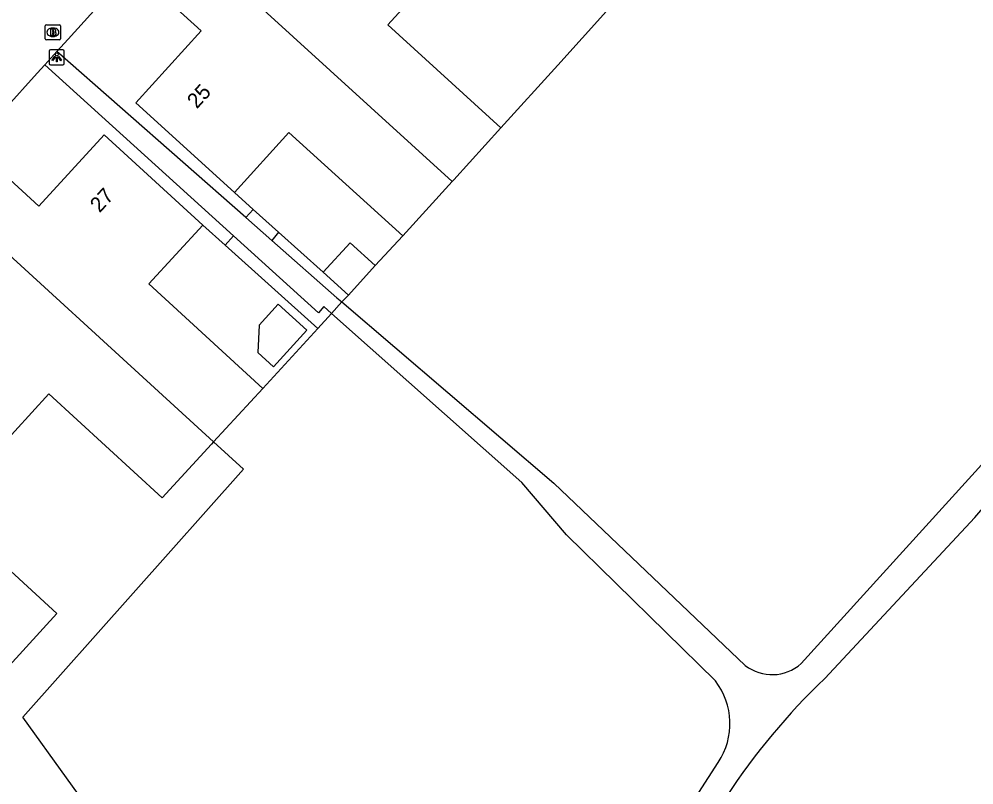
# Model space of a CAD drawing. Extents: x 158474 to 159560, y 388525 to 389605.
# Drawn here: x 158776 to 158838.9, y 389093.6 to 389144.1 of the extents above; entities that cross this region are included whole.
import ezdxf

# ---------------------------------------------------------------- set-up
doc = ezdxf.new("R2010")
doc.units = 0
for name, color, linetype in [('IMGEO_Brandkraan', 7, 'Continuous'), ('IMGEO_Erf', 7, 'Continuous'), ('IMGEO_Gemengd_bos', 7, 'Continuous'), ('IMGEO_Groenvoorziening', 7, 'Continuous'), ('IMGEO_Lichtpunt', 7, 'Continuous'), ('IMGEO_Loofbos', 7, 'Continuous'), ('IMGEO_Pand', 7, 'Continuous'), ('IMGEO_Pand_nummerreeks', 7, 'Continuous'), ('IMGEO_Rijbaan_lokaal_open', 7, 'Continuous'), ('IMGEO_Voetpad_halfverhard', 7, 'Continuous'), ('IMGEO_Voetpad_open', 7, 'Continuous')]:
    doc.layers.add(name, color=color, linetype=linetype)

msp = doc.modelspace()

# ---------------------------------------------------------------- linework, layer by layer
at = {"layer": 'IMGEO_Brandkraan'}
for p, q in [((158777.729, 389142.755), (158777.729, 389143.607)), ((158777.804, 389143.681), (158778.656, 389143.681)), ((158778.217, 389143.461), (158778.242, 389143.461)), ((158778.73, 389143.607), (158778.73, 389142.755)), ((158778.24, 389142.901), (158778.215, 389142.901)), ((158778.656, 389142.681), (158777.804, 389142.681))]:
    msp.add_line(p, q, dxfattribs=at)
for points in [[(158777.729, 389142.755), (158777.729, 389143.607)], [(158777.804, 389143.681), (158778.656, 389143.681)], [(158778.73, 389143.607), (158778.73, 389142.755)], [(158778.077, 389143.381), (158778.077, 389142.981), (158778.29, 389142.981)], [(158778.308, 389143.381), (158778.077, 389143.381)], [(158778.256, 389143.3), (158778.202, 389143.3), (158778.202, 389143.224)], [(158778.202, 389143.224), (158778.255, 389143.224)], [(158778.264, 389143.148), (158778.202, 389143.148), (158778.202, 389143.067)], [(158778.202, 389143.067), (158778.264, 389143.067)], [(158778.656, 389142.681), (158777.804, 389142.681)]]:
    msp.add_lwpolyline(points, dxfattribs=at)
for centre, radius, start, end in [((158777.806, 389143.605), 0.0765, 91.55205, 178.44795), ((158777.806, 389143.605), 0.0765, 91.55205, 178.44795), ((158778.654, 389143.605), 0.0765, 1.55205, 88.44795), ((158778.654, 389143.605), 0.0765, 1.55205, 88.44795), ((158778.257, 389143.262), 0.0379, 267.82845, 90.93552), ((158778.265, 389143.107), 0.0404, 269.87594, 90.50774), ((158778.296, 389143.232), 0.251, 268.66757, 293.53466), ((158778.312, 389143.236), 0.145, 59.4692, 91.53667), ((158778.337, 389143.283), 0.0922, 285.51372, 58.15012), ((158778.342, 389143.091), 0.105, 301.31148, 78.98903), ((158777.806, 389142.757), 0.0765, 181.55205, 268.44795), ((158777.806, 389142.757), 0.0765, 181.55205, 268.44795), ((158778.654, 389142.757), 0.0765, 271.55205, 358.44795), ((158778.654, 389142.757), 0.0765, 271.55205, 358.44795)]:
    msp.add_arc(centre, radius, start, end, dxfattribs=at)
for centre, major_axis, ratio, start_param, end_param in [((158778.216, 389143.181), (-0.387, 0.002), 0.722429, 4.712389, 7.853982), ((158778.241, 389143.181), (-0.39, 0.002), 0.717154, 1.570796, 4.712389)]:
    msp.add_ellipse(centre, major_axis=major_axis, ratio=ratio, start_param=start_param, end_param=end_param, dxfattribs=at)
at = {"layer": 'IMGEO_Erf'}
for points in [[(158790.19, 389132.623), (158791.426, 389131.502)], [(158789.58, 389129.136), (158788.104, 389130.461)]]:
    msp.add_lwpolyline(points, dxfattribs=at)
at = {"layer": 'IMGEO_Gemengd_bos'}
for points in [[(158807.753, 389136.882), (158811.49, 389141.014), (158814.701, 389144.565)], [(158801.279, 389129.76), (158799.471, 389127.8)], [(158797.699, 389125.851), (158797.266, 389125.409)]]:
    msp.add_lwpolyline(points, dxfattribs=at)
at = {"layer": 'IMGEO_Groenvoorziening'}
for points in [[(158790.125, 389129.762), (158789.58, 389129.136)], [(158796.041, 389127.359), (158793.089, 389129.994)], [(158795.685, 389123.654), (158789.58, 389129.136)]]:
    msp.add_lwpolyline(points, dxfattribs=at)
at = {"layer": 'IMGEO_Lichtpunt'}
for p, q in [((158777.985, 389141.933), (158777.985, 389141.126)), ((158777.985, 389141.933), (158777.985, 389141.126)), ((158778.887, 389142.028), (158778.079, 389142.028)), ((158778.887, 389142.028), (158778.079, 389142.028)), ((158778.981, 389141.126), (158778.981, 389141.933)), ((158778.981, 389141.126), (158778.981, 389141.933)), ((158778.079, 389141.032), (158778.887, 389141.032)), ((158778.079, 389141.032), (158778.887, 389141.032))]:
    msp.add_line(p, q, dxfattribs=at)
for points in [[(158778.359, 389141.597), (158778.398, 389141.569), (158778.21, 389141.307), (158778.172, 389141.334), (158778.359, 389141.597)], [(158778.461, 389141.549), (158778.508, 389141.549), (158778.508, 389141.227), (158778.461, 389141.227), (158778.461, 389141.549)], [(158778.571, 389141.569), (158778.609, 389141.596), (158778.796, 389141.334), (158778.757, 389141.306), (158778.571, 389141.569)]]:
    msp.add_lwpolyline(points, dxfattribs=at)
msp.add_circle((158778.484, 389141.731), 0.0994, dxfattribs=at)
for centre, start, end in [((158778.079, 389141.933), 90, 180), ((158778.079, 389141.933), 90, 180), ((158778.887, 389141.933), 0, 90), ((158778.887, 389141.933), 0, 90), ((158778.079, 389141.126), 180, 270), ((158778.079, 389141.126), 180, 270), ((158778.887, 389141.126), 270, 0), ((158778.887, 389141.126), 270, 360)]:
    msp.add_arc(centre, 0.0946, start, end, dxfattribs=at)
at = {"layer": 'IMGEO_Loofbos'}
for points in [[(158796.579, 389124.646), (158795.685, 389123.654)], [(158795.685, 389123.654), (158792.058, 389119.706)], [(158781.994, 389090.017), (158776.247, 389098.029), (158790.784, 389114.383), (158788.821, 389116.176)]]:
    msp.add_lwpolyline(points, dxfattribs=at)
at = {"layer": 'IMGEO_Pand'}
for points in [[(158786.016, 389150.231), (158804.546, 389133.353)], [(158790.19, 389132.623), (158783.685, 389138.536), (158788.004, 389143.287), (158783.46, 389147.419)], [(158803.803, 389147.531), (158800.29, 389143.666), (158807.753, 389136.882)], [(158801.279, 389129.76), (158793.782, 389136.575), (158790.19, 389132.623)], [(158807.753, 389136.882), (158804.643, 389133.46), (158804.546, 389133.353)], [(158772.904, 389135.737), (158777.295, 389131.711), (158781.609, 389136.416), (158788.104, 389130.461)], [(158804.546, 389133.353), (158801.279, 389129.76)], [(158770.397, 389133.003), (158788.821, 389116.176)], [(158788.104, 389130.461), (158784.552, 389126.588), (158792.058, 389119.706)], [(158799.471, 389127.8), (158797.812, 389129.308), (158796.041, 389127.359)], [(158799.471, 389127.8), (158797.699, 389125.851)], [(158796.041, 389127.359), (158797.699, 389125.851)], [(158791.738, 389122.062), (158792.76, 389121.133), (158794.954, 389123.547), (158793.08, 389125.251), (158791.824, 389123.87), (158791.738, 389122.062)], [(158792.058, 389119.706), (158788.821, 389116.176)], [(158788.821, 389116.176), (158788.679, 389116.021), (158785.432, 389112.48), (158777.954, 389119.336), (158774.578, 389115.654)], [(158774.578, 389115.654), (158770.989, 389111.741), (158778.5, 389104.854), (158775.345, 389101.412)]]:
    msp.add_lwpolyline(points, dxfattribs=at)
at = {"layer": 'IMGEO_Rijbaan_lokaal_open'}
for points in [[(158778.486, 389141.915), (158779.226, 389142.733), (158783.46, 389147.419)], [(158777.698, 389141.042), (158778.486, 389141.915)], [(158772.904, 389135.737), (158777.199, 389140.49), (158777.698, 389141.042)]]:
    msp.add_lwpolyline(points, dxfattribs=at)
at = {"layer": 'IMGEO_Voetpad_halfverhard'}
for points in [[(158827.533, 389101.555), (158846.783, 389122.782), (158849.381, 389126.955)], [(158797.266, 389125.409), (158811.239, 389113.455), (158823.843, 389101.437)], [(158829.083, 389100.567), (158838.982, 389111.199), (158851.235, 389125.547), (158852.333, 389125.541)], [(158821.882, 389100.424), (158812.081, 389110.051), (158809.123, 389113.496), (158796.579, 389124.646)], [(158817.024, 389087.185), (158822.071, 389095.043)]]:
    msp.add_lwpolyline(points, dxfattribs=at)
for centre, radius, start, end in [((158825.617, 389103.727), 2.897, 232.24525, 311.41794), ((158818.206, 389097.601), 4.635, 326.50107, 37.52214), ((158859.453, 389068.679), 44.036, 133.60357, 146.77948)]:
    msp.add_arc(centre, radius, start, end, dxfattribs=at)
at = {"layer": 'IMGEO_Voetpad_open'}
for points in [[(158790.937, 389130.966), (158778.486, 389141.915)], [(158777.698, 389141.042), (158790.125, 389129.762)], [(158791.426, 389131.502), (158790.937, 389130.966)], [(158791.426, 389131.502), (158793.089, 389129.994)], [(158790.937, 389130.966), (158792.659, 389129.452)], [(158796.579, 389124.646), (158796.076, 389125.093), (158795.725, 389124.679), (158790.125, 389129.762)], [(158793.089, 389129.994), (158792.659, 389129.452)], [(158792.659, 389129.452), (158796.947, 389125.682), (158797.266, 389125.409)], [(158796.579, 389124.646), (158797.266, 389125.409)]]:
    msp.add_lwpolyline(points, dxfattribs=at)

# ---------------------------------------------------------------- texts
at = {"layer": 'IMGEO_Pand_nummerreeks'}
for s, rotation, p in [('25', 47.72691, (158787.715, 389138.094)), ('27', 47.48239, (158781.312, 389131.239))]:
    msp.add_text(s, height=1, rotation=rotation, dxfattribs=at).set_placement(p)

doc.saveas('drawing.dxf')
